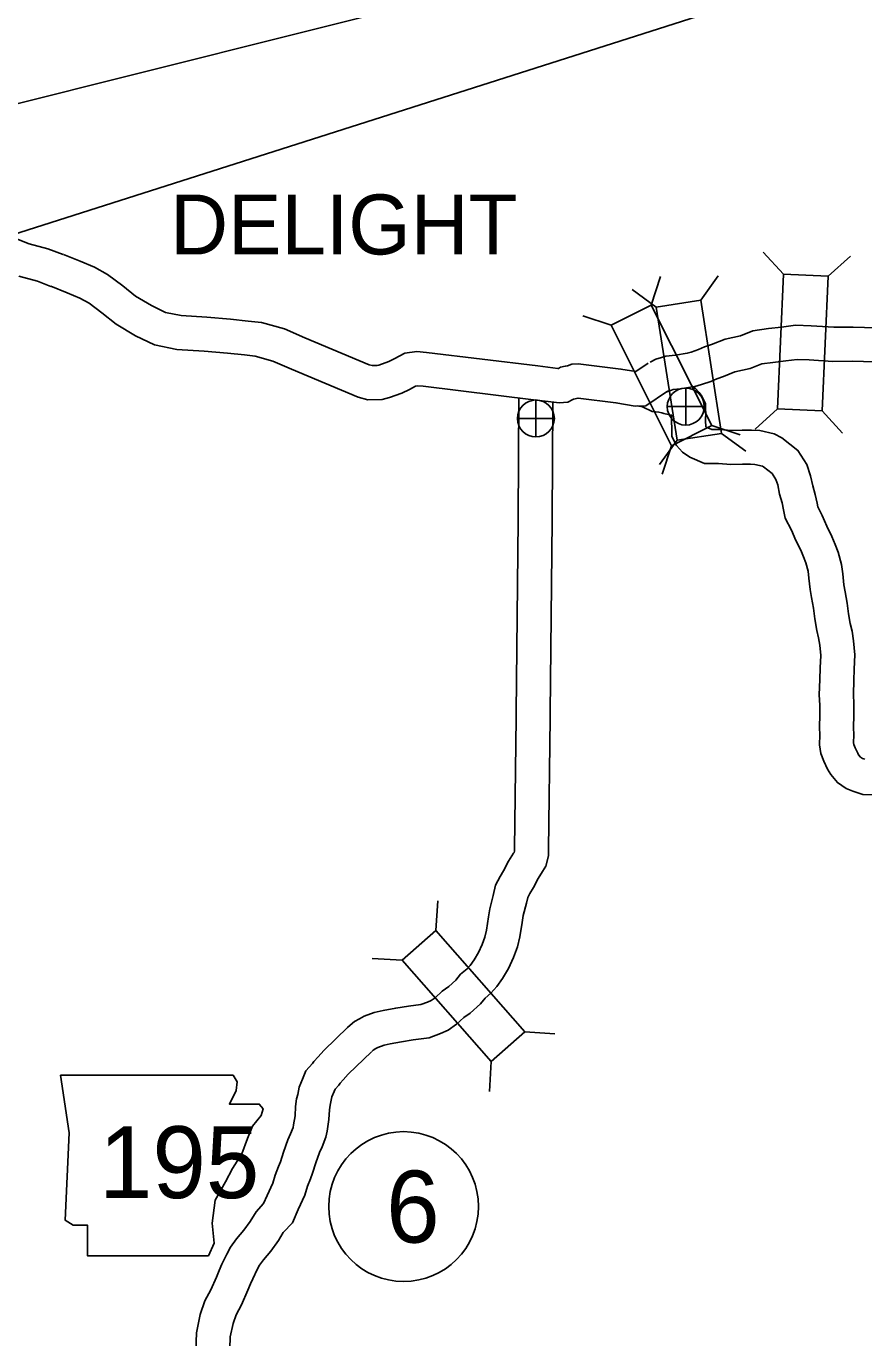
# Model space of a CAD drawing. Extents: x 79818 to 83933, y 50884 to 53307.
# Drawn here: x 81261.3 to 81359.7, y 53002.4 to 53156.5 of the extents above; entities that cross this region are included whole.
import ezdxf

# ---------------------------------------------------------------- set-up
doc = ezdxf.new("R2010")
doc.units = 0
for name, color, linetype in [('Default', 7, 'Continuous'), ('Level 10', 7, 'Continuous'), ('Level 20', 7, 'Continuous'), ('Level 21', 7, 'Continuous'), ('Level 26', 7, 'Continuous'), ('Level 27', 7, 'Continuous'), ('Level 6', 7, 'Continuous')]:
    doc.layers.add(name, color=color, linetype=linetype)

msp = doc.modelspace()

# ---------------------------------------------------------------- linework, layer by layer
at = {"layer": 'Default'}
for p in [(81049.64, 53094.55), (81071.88, 53072.06)]:
    msp.add_line(p, (81483.45, 53203.33), dxfattribs=at)
at = {"layer": 'Level 10'}
for points in [[(81259.58, 53131.71), (81261.66, 53130.9), (81263.85, 53130.32), (81265.64, 53129.64)], [(81265.67, 53129.63), (81267.63, 53128.84), (81269.33, 53128.14), (81270.86, 53127.3), (81272.67, 53125.95), (81274.16, 53124.73), (81276.03, 53123.64), (81277.68, 53122.84), (81279.52, 53122.47), (81282.53, 53122.27), (81285.33, 53122.04), (81287.39, 53121.82), (81288.95, 53121.65), (81291.65, 53120.91), (81294.06, 53119.84), (81301.61, 53116.68), (81301.97, 53116.59), (81302.54, 53116.59), (81302.76, 53116.66), (81303.93, 53117.07), (81304.56, 53117.37), (81305.82, 53118.04), (81307.21, 53118.23), (81308.33, 53118.14), (81321.43, 53116.55)], [(81260.42, 53127.09), (81262.63, 53126.51), (81264.21, 53125.9)], [(81264.18, 53125.91), (81266.12, 53125.14), (81267.6, 53124.52), (81268.7, 53123.93), (81270.21, 53122.8), (81271.86, 53121.45), (81274.14, 53120.1), (81276.4, 53119.02), (81278.99, 53118.5), (81282.23, 53118.28), (81284.95, 53118.06), (81286.96, 53117.84), (81288.2, 53117.71), (81290.3, 53117.13), (81292.47, 53116.17), (81300.32, 53112.88), (81301.46, 53112.58), (81303.13, 53112.59), (81304, 53112.85), (81305.45, 53113.36), (81306.36, 53113.79), (81307.07, 53114.17), (81307.33, 53114.21), (81307.95, 53114.16), (81320.94, 53112.58)], [(81334.63, 53117.01), (81335.29, 53117.34), (81335.98, 53117.54), (81336.49, 53117.7), (81337.61, 53117.82), (81339, 53118.04), (81339.44, 53118.17), (81340.32, 53118.48), (81341.03, 53118.78), (81341.83, 53119.06), (81343.43, 53119.7), (81345.23, 53120.07), (81346.71, 53120.67), (81348.53, 53120.93), (81350.06, 53121.11), (81351.7, 53121.34), (81353.54, 53121.25), (81356.21, 53121.09), (81358.49, 53121.12), (81361.17, 53121.03)], [(81336.43, 53113.44), (81336.74, 53113.6), (81337.14, 53113.71), (81337.32, 53113.77), (81338.14, 53113.86), (81339.89, 53114.13), (81340.67, 53114.36), (81341.76, 53114.74), (81342.48, 53115.05), (81343.24, 53115.32), (81344.58, 53115.86), (81346.4, 53116.23), (81347.76, 53116.78), (81349.04, 53116.96), (81350.57, 53117.14), (81351.89, 53117.32), (81353.33, 53117.26), (81356.11, 53117.09), (81358.44, 53117.12), (81360.96, 53117.03)], [(81334.41, 53116.88), (81332.94, 53115.89), (81331.19, 53116.19), (81326.18, 53116.81), (81325.42, 53116.77), (81324.92, 53116.58), (81324.65, 53116.51), (81324.1, 53116.39), (81323.85, 53116.24), (81323.79, 53116.25), (81321.43, 53116.55)], [(81319.18, 53112.85), (81319.12, 53098.61), (81319.12, 53098.37)], [(81336.65, 53113.57), (81334.11, 53111.85), (81332.87, 53111.84), (81330.61, 53112.23), (81326.17, 53112.78), (81325.62, 53112.63), (81325.55, 53112.61), (81324.97, 53112.28), (81323.95, 53112.21), (81323.31, 53112.28), (81320.94, 53112.58)], [(81339.55, 53114.13), (81339.97, 53113.9), (81340.38, 53113.42), (81340.72, 53112.99), (81341.15, 53112.12), (81341.15, 53111.43), (81341.19, 53111), (81341.15, 53110.28), (81341.15, 53109.92), (81341.16, 53109.63), (81341.18, 53109.4), (81341.22, 53109.37), (81341.86, 53109.09), (81342.82, 53109.08), (81344.21, 53108.98), (81345.44, 53109.01), (81346.55, 53109.01), (81347.52, 53108.95), (81349.19, 53108.56), (81350.1, 53108.12), (81351.99, 53106.63), (81353.04, 53104.96), (81353.49, 53103.65), (81353.74, 53102.45), (81354.03, 53101.43), (81354.25, 53100.42), (81354.33, 53099.98), (81354.85, 53098.99), (81355.39, 53097.73), (81355.99, 53096.51), (81356.37, 53095.57), (81356.72, 53094.66), (81357.12, 53093.21), (81357.26, 53092.12), (81357.41, 53090.84), (81357.55, 53090.01), (81357.77, 53088.68), (81357.94, 53087.43), (81358.14, 53086.28), (81358.36, 53085.4), (81358.54, 53084.26), (81358.69, 53082.62), (81358.61, 53080.92), (81358.56, 53079.58), (81358.52, 53077.98), (81358.58, 53076.81), (81358.57, 53075.54), (81358.54, 53074.08), (81358.56, 53073.22), (81358.53, 53072.26), (81358.56, 53072.08), (81358.71, 53071.7), (81359.02, 53071.06), (81359.13, 53070.86), (81359.35, 53070.6), (81359.57, 53070.45), (81359.85, 53070.34)], [(81323.18, 53112.32), (81323.12, 53098.59), (81323.12, 53098.37)], [(81334.87, 53111.2), (81333.72, 53111.76), (81333.11, 53111.88)], [(81334.87, 53111.2), (81335.67, 53111.11), (81336, 53111.04), (81336.24, 53110.98), (81336.74, 53110.85), (81337.1, 53110.78), (81337.17, 53110.76), (81337.15, 53110.42), (81337.14, 53109.86), (81337.17, 53109.37), (81337.19, 53109.07), (81337.18, 53108.27), (81337.73, 53107.19), (81338.44, 53106.41), (81339.31, 53105.84), (81341.02, 53105.1), (81342.65, 53105.09), (81344.11, 53104.98), (81345.49, 53105.01), (81346.43, 53105.01), (81346.93, 53104.98), (81347.84, 53104.77), (81347.96, 53104.71), (81348.97, 53103.91), (81349.41, 53103.22), (81349.63, 53102.59), (81349.85, 53101.5), (81350.15, 53100.47), (81350.32, 53099.64), (81350.5, 53098.67), (81351.24, 53097.27), (81351.76, 53096.06), (81352.33, 53094.89), (81352.64, 53094.11), (81352.92, 53093.4), (81353.19, 53092.43), (81353.29, 53091.63), (81353.45, 53090.27), (81353.6, 53089.36), (81353.82, 53088.08), (81353.99, 53086.82), (81354.22, 53085.47), (81354.43, 53084.62), (81354.57, 53083.76), (81354.68, 53082.52), (81354.61, 53081.09), (81354.56, 53079.71), (81354.51, 53077.92), (81354.58, 53076.71), (81354.57, 53075.61), (81354.53, 53074.07), (81354.56, 53073.22), (81354.53, 53072.02), (81354.67, 53071.03), (81355.04, 53070.1), (81355.48, 53069.18), (81355.85, 53068.56), (81356.64, 53067.6), (81357.68, 53066.91), (81358.46, 53066.58), (81359.62, 53066.2), (81361.06, 53066.15)], [(81319.12, 53098.37), (81318.88, 53075.83), (81318.89, 53075.19), (81318.7, 53059.8), (81318.69, 53059.54), (81318.65, 53059.39), (81318.59, 53059.29), (81318, 53058.36), (81317.4, 53057.22), (81317.02, 53056.55), (81316.46, 53055.56), (81316.19, 53054.34), (81315.79, 53052.75), (81315.65, 53051.81), (81315.4, 53050.28), (81315.2, 53049.44), (81314.89, 53048.59), (81314.44, 53047.63), (81313.93, 53046.78), (81313.47, 53046.13), (81313.11, 53045.73), (81312.36, 53045.1), (81311.78, 53044.37), (81310.96, 53043.65), (81310.19, 53043.09), (81309.37, 53042.33), (81308.91, 53042.01), (81308.48, 53041.82), (81307.69, 53041.53), (81306.22, 53041.33), (81304.73, 53041.1), (81303.25, 53040.82), (81302.21, 53040.59), (81301.03, 53040.14), (81300.47, 53039.86), (81299.89, 53039.54), (81299.36, 53039.1), (81299.08, 53038.82)], [(81323.12, 53098.37), (81322.88, 53075.82), (81322.89, 53075.17), (81322.7, 53059.73), (81322.68, 53059.01), (81322.38, 53057.79), (81321.97, 53057.14), (81321.47, 53056.35), (81320.91, 53055.29), (81320.5, 53054.57), (81320.24, 53054.11), (81320.09, 53053.43), (81319.72, 53051.97), (81319.6, 53051.18), (81319.32, 53049.49), (81319.04, 53048.3), (81318.59, 53047.06), (81317.98, 53045.74), (81317.27, 53044.58), (81316.6, 53043.64), (81315.92, 53042.87), (81315.24, 53042.29), (81314.68, 53041.59), (81313.46, 53040.52), (81312.73, 53039.99), (81311.88, 53039.2), (81310.88, 53038.52), (81310, 53038.12), (81308.66, 53037.62), (81306.79, 53037.37), (81305.41, 53037.16), (81304.06, 53036.9), (81303.36, 53036.74), (81302.63, 53036.46), (81302.31, 53036.31), (81302.15, 53036.22), (81302.07, 53036.15), (81301.92, 53036)], [(81299.11, 53038.85), (81296.29, 53036.13), (81295.62, 53035.4), (81295.1, 53034.83), (81294.94, 53034.6), (81294.15, 53033.75), (81293.76, 53032.77), (81293.39, 53031.82), (81293.21, 53030.97), (81293.08, 53030.43), (81292.96, 53029.55), (81292.9, 53028.46), (81292.73, 53027.39), (81292.66, 53027.08), (81292.37, 53026.33), (81292.06, 53025.63), (81291.56, 53024.18), (81291.2, 53023.06), (81290.97, 53022.48), (81290.58, 53021.47), (81290.29, 53020.52), (81289.64, 53019.08), (81289.21, 53018.14), (81288.31, 53017.16), (81287.61, 53016.03), (81286.89, 53015.02), (81286.03, 53014.01), (81285.32, 53013.01), (81284.89, 53012.2), (81284.31, 53011.01), (81283.98, 53010.29), (81283.66, 53009.49), (81283.01, 53007.99), (81282.31, 53006.7), (81281.75, 53005.12), (81281.3, 53002.94), (81281.19, 52999.77)], [(81301.89, 53035.97), (81299.16, 53033.34), (81298.57, 53032.69), (81298.2, 53032.3), (81298.04, 53032.07), (81297.6, 53031.59), (81297.49, 53031.32), (81297.24, 53030.67), (81297.11, 53030.1), (81297.02, 53029.7), (81296.95, 53029.17), (81296.88, 53028.03), (81296.67, 53026.66), (81296.51, 53025.94), (81296.07, 53024.79), (81295.79, 53024.16), (81295.36, 53022.91), (81294.96, 53021.71), (81294.7, 53021.03), (81294.36, 53020.17), (81294.05, 53019.12), (81293.28, 53017.43), (81292.58, 53015.89), (81291.51, 53014.73), (81290.94, 53013.81), (81290.05, 53012.56), (81289.19, 53011.54), (81288.73, 53010.91), (81288.46, 53010.39), (81287.93, 53009.3), (81287.66, 53008.72), (81287.36, 53007.95), (81286.6, 53006.24), (81285.98, 53005.07), (81285.61, 53004.04), (81285.29, 53002.47), (81285.2, 52999.79)]]:
    msp.add_lwpolyline(points, dxfattribs=at)
at = {"layer": 'Level 20'}
for p, q in [((81350.3, 53127.33), (81347.92, 53129.92)), ((81355.57, 53127.09), (81358.17, 53129.46)), ((81334.76, 53123.7), (81335.86, 53127.04)), ((81340.57, 53124.28), (81342.64, 53127.12)), ((81335.35, 53123.46), (81332.51, 53125.53)), ((81330.04, 53121.33), (81326.7, 53122.43)), ((81349.59, 53111.5), (81346.99, 53109.13)), ((81354.86, 53111.27), (81357.24, 53108.67)), ((81341.87, 53109.55), (81345.21, 53108.44)), ((81343.02, 53108.63), (81345.86, 53106.55)), ((81337.8, 53107.81), (81335.73, 53104.97)), ((81337.15, 53107.18), (81336.05, 53103.83)), ((81309.46, 53050.21), (81309.68, 53053.72)), ((81305.49, 53046.72), (81301.98, 53046.95)), ((81319.92, 53038.32), (81323.44, 53038.1)), ((81315.96, 53034.83), (81315.74, 53031.32))]:
    msp.add_line(p, q, dxfattribs=at)
for points in [[(81354.86, 53111.27), (81355.57, 53127.09), (81350.3, 53127.33), (81349.59, 53111.5)], [(81341.87, 53109.55), (81334.76, 53123.7), (81330.04, 53121.33), (81337.15, 53107.18)], [(81335.35, 53123.46), (81337.8, 53107.81), (81343.02, 53108.63), (81340.57, 53124.28)], [(81319.92, 53038.32), (81309.46, 53050.21), (81305.49, 53046.72), (81315.96, 53034.83)]]:
    msp.add_lwpolyline(points, close=True, dxfattribs=at)
at = {"layer": 'Level 21'}
msp.add_lwpolyline([(81265.34, 53033.22), (81266.35, 53026.45), (81265.9, 53016.18), (81266.81, 53015.62), (81268.5, 53015.62), (81268.5, 53012.01), (81282.71, 53012.01), (81283.39, 53013.48), (81283.16, 53015.85), (81283.5, 53018.55), (81284.74, 53020.7), (81285.53, 53022.27), (81286.66, 53023.97), (81287.33, 53025.77), (81287.9, 53027.24), (81288.91, 53028.48), (81289.14, 53029.27), (81288.69, 53029.83), (81285.19, 53029.83), (81285.98, 53031.41), (81286.09, 53032.43), (81285.62, 53033.21)], close=True, dxfattribs=at)
at = {"layer": 'Level 26'}
for p, q in [((81338.81, 53109.61), (81338.81, 53113.94)), ((81321.2, 53108.21), (81321.2, 53112.54)), ((81336.64, 53111.77), (81340.98, 53111.77)), ((81319.03, 53110.38), (81323.37, 53110.38))]:
    msp.add_line(p, q, dxfattribs=at)
for centre in [(81338.81, 53111.77), (81321.2, 53110.38)]:
    msp.add_circle(centre, 2.17, dxfattribs=at)
at = {"layer": 'Level 27'}
msp.add_circle((81305.66, 53017.79), 8.8, dxfattribs=at)

# ---------------------------------------------------------------- texts
at = {"layer": 'Level 21'}
msp.add_text('195', height=8.448, dxfattribs=at).set_placement((81269.85, 53018.78))
at = {"layer": 'Level 27'}
msp.add_text('6', height=8.45, dxfattribs=at).set_placement((81303.61, 53013.56))
at = {"layer": 'Level 6'}
msp.add_text('DELIGHT', height=7.04, dxfattribs=at).set_placement((81278.23, 53129.65))

doc.saveas('drawing.dxf')
